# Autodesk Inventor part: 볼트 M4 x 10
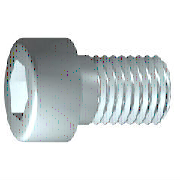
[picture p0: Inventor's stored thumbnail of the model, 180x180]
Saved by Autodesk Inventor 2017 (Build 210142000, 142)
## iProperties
IsCustomPart: 0
Created: 2012-02
Part Number: 볼트 M4 x 10
Material: 스테인리스강
Description: 6각 소켓 머리 캡 나사
Document SubType Name: Modeling
Standard: ISO 4762
Designer: mduedu
Standard Revision: Fourth edition 2004-03-01
Standards Organization: ISO
Language: ko-KR
Size Designation: M4 x 10
Categories: <MemberInstance><Categories><Category DisplayName="조임쇠" InternalName="e4da775c-781d-43d5-af7c-5136215cf5a6" Mnemonic="FSTN"><Category DisplayName="볼트" InternalN
Density: 8.08 g/cm^3
Appearance: 반광택
Mass: 2.09412 g
Surface Area: 3.0572 cm^2
Volume: 0.259174 cm^3
Author: mduedu
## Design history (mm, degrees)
sketch "스케치1"
  geometry: L1 (-1, 0)-(10, 0); L2 (10, 0)-(10, 2); L3 (10, 2)-(1.75, 2); L4 (1.75, 2)-(1.32, 2); L5 (1.32, 2)-(0, 2); L6 (0, 2)-(0, 3.5); L7 (0, 3.5)-(-4, 3.5); L8 (-4, 3.5)-(-4, 1.732); L9 (-4, 1.732)-(-2, 1.732); L10 (-2, 1.732)-(-1, 0); L11 (-6.8, 0)-(12.8, 0) reference; L12 (0, -0.7)-(0, 4.2) reference; L13 (1.75, 2)-(0, 2)
  constraints: 22 end point, 6 parallel, 2 collinear, 2 perpendicular, 1 horizontal, 1 point on line
  dimensions: "d1" = 8.25 distance from line of L3.end L2 (= GEL); "d2" = 0.42952 distance of L4.end L3.end (computed from GAL); "d3" = 4 distance between parallel lines of L8 L6 (= KOH); "d4" = 2 distance of L8.end L9.end (= INTI); "d5" = 60 deg angle of L10 L1; "d6" = 4 diameter of L3 L1 (= GD); "d7" = 4 diameter of L5 L1 (= BDM); "d8" = 3.4641 diameter of L9 L1 (= 1.1547 x SW); "d9" = 7 diameter of L7 L1 (= KOD); "d26" = 10 distance between parallel lines of L12 L2 (= NLG)
revolve "본체" sketch "스케치1" stored, may be unused: angle "d10" = 90 deg
sketch "스케치2"
  geometry: L1 (0, -4.9)-(0, 4.9) reference; L2 (-4.9, 0)-(4.9, 0) reference; L3 (1.732, 0)-(0.866, -1.5); L4 (0.866, -1.5)-(-0.866, -1.5); L5 (-0.866, -1.5)-(-1.732, 0); L6 (-1.732, 0)-(-0.866, 1.5); L7 (-0.866, 1.5)-(0.866, 1.5); L8 (0.866, 1.5)-(1.732, 0); 2 further points
  constraints: 12 end point, 1 coincident, 1 horizontal alignment, 1 point on line, 12 other
extrude "슬롯" join sketch "스케치2" stored distance "d11" = 10; taper "d12" = 0 deg
workplane "Work Plane1"
fillet "Fillet2" dims "d30" = 0.1 (= R)
body "Solid1"
fillet "모깎기1" dims "d17" = 0.4 (= RR)
feature "스레드" dims "d13" = 8.25 (= GEL), "d14" = 0
chamfer "모따기1" distance "d15" = 0.42941 (= -0.5 x SPD + 0.5 x GD); stored, may be unused: second distance "d16" = 0.42941 (= GUL), angle "d27" = 45 deg
other parameters: "GD" = 4 [user parameter; used in 2 equation terms], "NLG" = 10 [user parameter; used in 1 equation term], "GEL" = 8.25 [user parameter; used in 2 equation terms], "KOD" = 7 [user parameter; used in 1 equation term], "KOH" = 4 [user parameter; used in 1 equation term], "INTI" = 2 [user parameter; used in 1 equation term], "GAL" = 0.42941 (= 0.61345 x PTC) [user parameter; used in 1 equation term], "GUL" = 0.42941 (= 0.61345 x PTC) [user parameter; used in 1 equation term], "BDM" = 4 (= NND) [user parameter; used in 1 equation term], "SW" = 3 [user parameter; used in 2 equation terms], "RR" = 0.4 [user parameter; used in 1 equation term], "SPD" = 3.14117 (= NND - 1.2269 x PTC) [user parameter; used in 1 equation term], "d19" = 0, "d28" = 0, "d29" = 0, "R" = 0.1 [user parameter; used in 1 equation term], "TOA" = 30 deg [user parameter], "GD1" = 3.14117 (= THREADDIA - 1.2269 x PTC) [user parameter], "THREADDIA" = 4 [user parameter; used in 1 equation term], "FAWI" = 45 deg [user parameter], "TPU" = 14.28571 (computed from PTC) [user parameter], "PTC" = 0.7 [user parameter; used in 5 equation terms], "NND" = 4 [user parameter; used in 2 equation terms], "E0" = 3.465 (= 1.155 x SW) [user parameter]
